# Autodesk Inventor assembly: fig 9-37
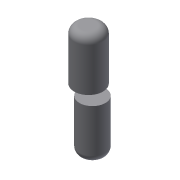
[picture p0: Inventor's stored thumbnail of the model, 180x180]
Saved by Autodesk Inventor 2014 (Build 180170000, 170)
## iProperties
Created: 2013-07
Part Number: fig 9-37
Document SubType Name: Assembly
Designer: CADCIM
Author: CADCIM
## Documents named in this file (3)
- E:\APS\Autodesk Inventor 2014-Project\inventor_2014_partfiles\Inventor_2014_prt\c09_Inv_2014_prt\c09_inv_2014_prt\fig 9-37.iam
- E:\APS\c09partfile\fig-9-37_1.ipt
- E:\APS\c09partfile\fig-9-37_2.ipt
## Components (2 placed, 2 different names)
1. fig-9-37_1:1
2. fig-9-37_2:1
